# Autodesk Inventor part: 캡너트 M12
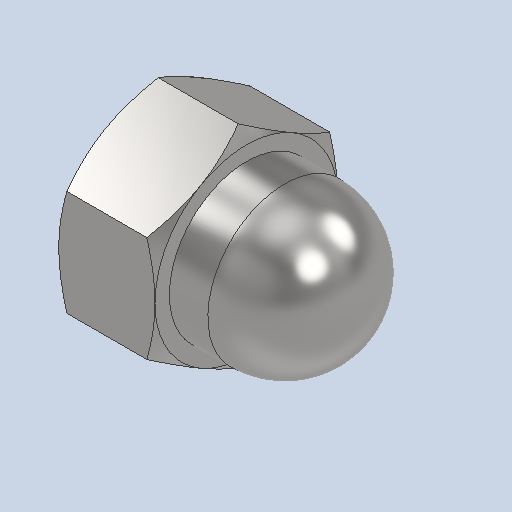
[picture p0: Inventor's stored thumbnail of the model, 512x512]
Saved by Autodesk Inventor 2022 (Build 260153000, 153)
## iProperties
Created: 2024-07
Part Number: 캡너트 M12
Material: 강철, 연강
Description: 6각 둥근캡 너트
Document SubType Name: Modeling
Designer: PC-01
Density: 7.85 g/cm^3
Appearance: 기본값
Author: jhkim
Sending System: Autodesk Inventor 2025
Preprocessor: ST-DEVELOPER v20
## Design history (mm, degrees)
feature "Solid1"
node "솔리드1"
